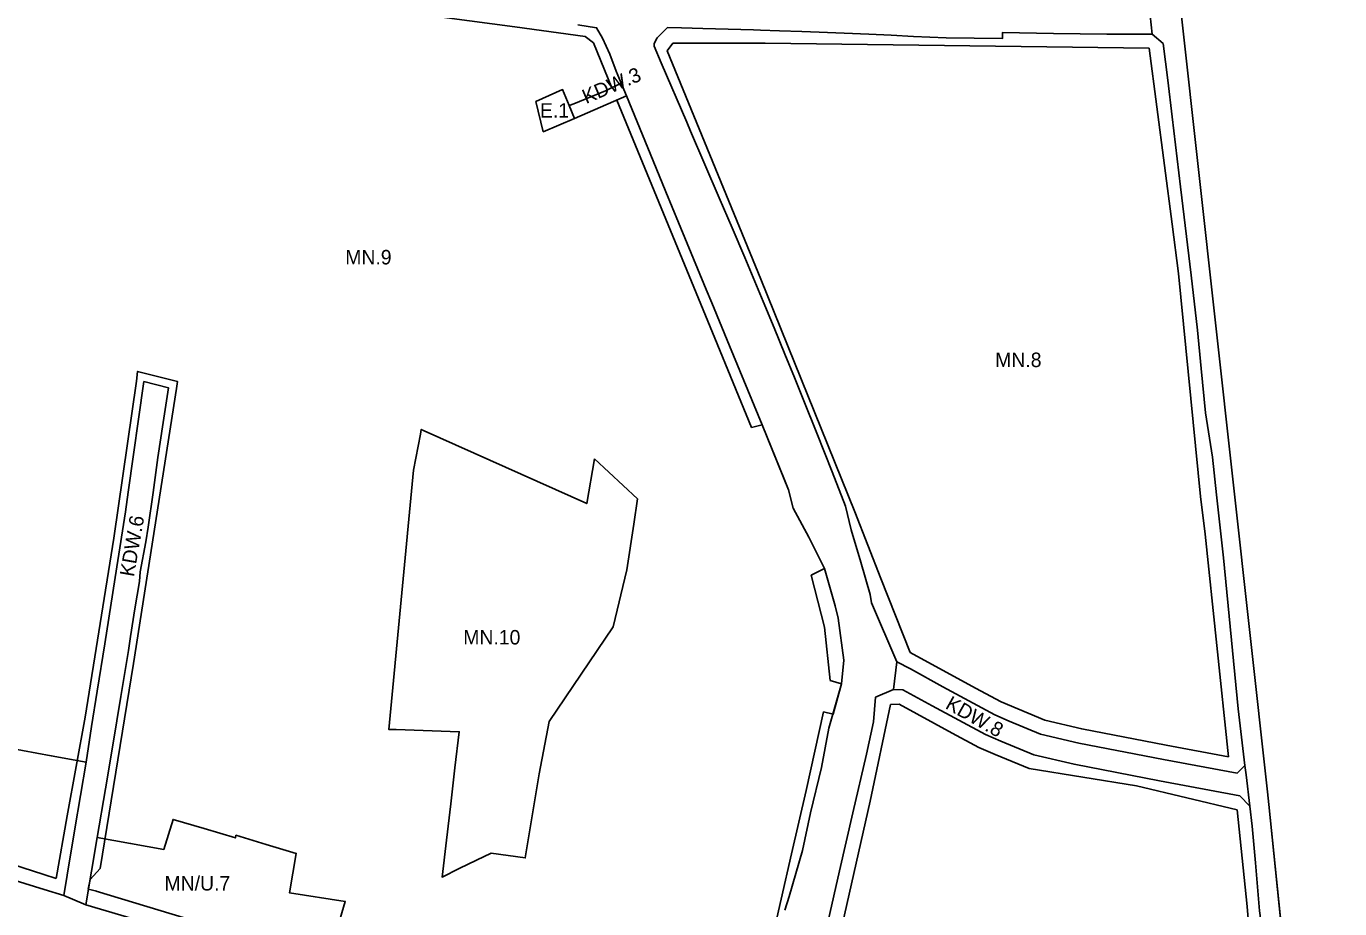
# Model space of a CAD drawing. Extents: x 7423274 to 7424514, y 5542390 to 5544261.
# Drawn here: x 7423885.8 to 7424248, y 5543366 to 5543609.4 of the extents above; entities that cross this region are included whole.
import ezdxf

# ---------------------------------------------------------------- set-up
doc = ezdxf.new("R2010")
doc.units = 0
for name, color, linetype in [('granica obszaru objętego planem', 7, 'Continuous'), ('LIN_Granica Planu', 7, 'Continuous'), ('linie rozgraniczające tereny o różnym przeznaczeniu lub różnych zasadach zagospodarowania', 7, 'Continuous'), ('nieprzekraczalna linia zabudowy', 7, 'Continuous'), ('oznaczenia terenów', 7, 'Continuous')]:
    doc.layers.add(name, color=color, linetype=linetype)

msp = doc.modelspace()

# ---------------------------------------------------------------- linework, layer by layer
at = {"layer": 'granica obszaru objętego planem'}
for p, q in [((7424204.36, 5543612.15), (7424228.15, 5543398.17)), ((7424228.15, 5543398.17), (7424228.51, 5543394.73)), ((7424228.51, 5543394.73), (7424242.62, 5543256.86))]:
    msp.add_line(p, q, dxfattribs=at)
at = {"layer": 'LIN_Granica Planu'}
for p, q in [((7424228.15, 5543398.17), (7424204.36, 5543612.15)), ((7424228.51, 5543394.73), (7424228.15, 5543398.17)), ((7424242.62, 5543256.86), (7424228.51, 5543394.73))]:
    msp.add_line(p, q, dxfattribs=at)
at = {"layer": 'linie rozgraniczające tereny o różnym przeznaczeniu lub różnych zasadach zagospodarowania'}
for p, q in [((7424195.16, 5543618.28), (7424196.31, 5543607.23)), ((7424036.98, 5543583.98), (7424051.34, 5543590.15))]:
    msp.add_line(p, q, dxfattribs=at)
for points in [[(7424129.39, 5544001.9), (7424129.8, 5543999.91), (7424131.7, 5543990.87), (7424133.97, 5543980.01), (7424148.11, 5543912.49), (7424163.08, 5543838.56), (7424169.46, 5543807.01), (7424175.57, 5543776.81), (7424186.15, 5543728.82), (7424192.74, 5543698.89), (7424202.07, 5543636.25), (7424204.36, 5543612.15), (7424228.15, 5543398.17), (7424228.51, 5543394.73), (7424242.62, 5543256.86), (7424248.04, 5543257.08)], [(7424037.96, 5543609.76), (7424043.11, 5543608.99), (7424044.74, 5543606.11), (7424046.74, 5543601.68), (7424048.53, 5543597), (7424049.9, 5543593.66)], [(7424125.94, 5543434.02), (7424118.89, 5543450.32), (7424118.56, 5543452.65), (7424115.95, 5543461.55), (7424113.34, 5543470.45), (7424111.76, 5543477.01), (7424108.05, 5543486.45), (7424103.86, 5543497.1), (7424100.24, 5543506.07), (7424097.65, 5543512.5), (7424095.05, 5543518.92), (7424092.04, 5543526.17), (7424089.03, 5543533.43), (7424083.99, 5543545.58), (7424080.46, 5543553.81), (7424076.92, 5543562.04), (7424069, 5543580.48), (7424067.95, 5543582.94), (7424060.94, 5543599.26), (7424059.02, 5543603.89), (7424058.97, 5543604.62), (7424059.79, 5543606.15), (7424062.64, 5543609), (7424066.54, 5543608.91), (7424069.47, 5543608.83), (7424072.4, 5543608.75), (7424079.41, 5543608.56), (7424086.42, 5543608.37), (7424088.27, 5543608.33), (7424093.54, 5543608.16), (7424099.74, 5543607.95), (7424102.12, 5543607.87), (7424104.51, 5543607.79), (7424111.35, 5543607.48), (7424118.19, 5543607.16), (7424124.36, 5543606.88), (7424130.53, 5543606.59), (7424135.03, 5543606.38), (7424139.53, 5543606.18), (7424147.27, 5543606.08), (7424155, 5543605.97), (7424155, 5543607.63), (7424169.1, 5543607.38), (7424176.45, 5543607.3), (7424183.79, 5543607.23), (7424196.31, 5543607.23)], [(7424062.64, 5543609), (7424062.64, 5543609)], [(7424183.79, 5543607.23), (7424183.79, 5543607.23)], [(7424196.31, 5543607.23), (7424199.37, 5543604.59), (7424200.59, 5543594.48), (7424201.82, 5543584.37), (7424204.16, 5543565.07), (7424207.11, 5543540.74), (7424208.8, 5543525.54), (7424209.82, 5543514.99), (7424210.99, 5543502.76), (7424212.93, 5543490.48), (7424214.06, 5543480.17), (7424216.01, 5543462.75), (7424220.04, 5543421.12), (7424221.9, 5543405.42)], [(7424049.9, 5543593.66), (7424045.57, 5543591.56), (7424036.87, 5543588.02), (7424035.55, 5543587.48)], [(7424049.9, 5543593.66), (7424051.34, 5543590.15)], [(7424035.55, 5543587.48), (7424033.73, 5543591.92), (7424030.04, 5543590.25), (7424026.36, 5543588.59), (7424028.4, 5543580.29), (7424032.69, 5543582.13), (7424036.98, 5543583.98)], [(7424051.34, 5543590.15), (7424058.7, 5543572.26), (7424062.2, 5543563.75), (7424065.7, 5543555.23), (7424073.3, 5543536.76), (7424074.84, 5543533.06), (7424079.75, 5543521.24), (7424088.72, 5543499.41), (7424094.76, 5543484.71), (7424096.03, 5543481.46), (7424097.35, 5543476.46), (7424101.62, 5543468.49), (7424106, 5543459.76), (7424108.91, 5543449.49), (7424109.7, 5543446.06), (7424111.33, 5543434.5), (7424110.64, 5543428.03), (7424107.14, 5543415.72), (7424105.13, 5543404.88), (7424102.13, 5543392.36), (7424099.9, 5543381.97), (7424096.17, 5543369.34), (7424095.06, 5543365.57)], [(7424035.55, 5543587.48), (7424036.98, 5543583.98)], [(7423905.4, 5543385.58), (7423907.67, 5543399.07), (7423909.69, 5543411.08), (7423911.89, 5543424.5), (7423913.98, 5543437.2), (7423914.54, 5543441.02), (7423915.79, 5543448.64), (7423917.05, 5543456.26), (7423917.27, 5543458.85), (7423918.77, 5543467.19), (7423919.48, 5543471.18), (7423920.8, 5543480.79), (7423922.13, 5543490.39), (7423923.57, 5543500.04), (7423925.01, 5543509.68), (7423918.27, 5543511.38), (7423918.27, 5543511.37), (7423913.94, 5543480.85), (7423913.17, 5543475.41), (7423910.78, 5543460.22), (7423907.46, 5543439.05), (7423905.4, 5543425.99), (7423903.86, 5543416.19), (7423902.32, 5543406.39)], [(7424042.54, 5543490.03), (7424040.38, 5543477.73), (7423995.58, 5543497.82), (7423994.75, 5543498.16), (7423994.5, 5543496.87), (7423992.59, 5543486.91), (7423989.19, 5543451.16), (7423985.79, 5543415.41), (7423987.79, 5543415.35), (7424005.23, 5543414.79), (7424004.05, 5543404.86), (7424002.88, 5543394.93), (7424001.68, 5543384.82), (7424000.48, 5543374.7), (7424005.25, 5543377.01), (7424010.02, 5543379.32), (7424014.05, 5543381.28), (7424018.75, 5543380.63), (7424023.44, 5543379.98), (7424024.84, 5543388.81), (7424027.28, 5543403.16), (7424029.98, 5543417.58), (7424047.66, 5543443.74), (7424051.4, 5543459.48), (7424053.33, 5543472.01), (7424054.41, 5543479.02), (7424042.54, 5543490.03)], [(7423762.1, 5543471.78), (7423763.2, 5543470.95), (7423772.9, 5543465.5), (7423780.62, 5543462.22), (7423788.34, 5543458.94), (7423794.18, 5543472.69), (7423802.28, 5543468.74), (7423810.38, 5543464.78), (7423806.73, 5543456.67), (7423803.07, 5543448.57), (7423810.25, 5543445.33), (7423819.48, 5543441.05), (7423824.09, 5543438.92), (7423829.37, 5543437.42), (7423834.65, 5543435.93), (7423831.92, 5543426.28), (7423830.43, 5543420.98), (7423849.77, 5543416.04), (7423868.85, 5543412.52), (7423892.72, 5543408.15), (7423902.32, 5543406.39)], [(7424124.99, 5543426.4), (7424125.94, 5543434.02)], [(7424125.94, 5543434.02), (7424129.66, 5543432.17), (7424138.57, 5543427.18), (7424152.95, 5543419.4), (7424156.89, 5543417.67), (7424165.5, 5543414.14), (7424176.06, 5543411.66), (7424199.45, 5543407.1), (7424219.74, 5543403.36), (7424221.9, 5543405.42)], [(7424092.5, 5543275.06), (7424095.41, 5543303.55), (7424095.87, 5543307.37), (7424097.46, 5543318.57), (7424098.68, 5543326.94), (7424100.22, 5543333.4), (7424101.76, 5543339.86), (7424103.33, 5543346.79), (7424104.9, 5543353.71), (7424110.13, 5543376.43), (7424113.79, 5543392.37), (7424117.5, 5543408.62), (7424119.5, 5543417.47), (7424120.06, 5543424.28), (7424124.99, 5543426.4)], [(7424120.06, 5543424.28), (7424120.06, 5543424.28)], [(7424124.99, 5543426.4), (7424127.58, 5543426.33), (7424135.67, 5543421.93), (7424150.31, 5543414), (7424154.55, 5543412.15), (7424163.66, 5543408.41), (7424174.8, 5543405.79), (7424198.34, 5543401.2), (7424220.49, 5543397.12), (7424223.21, 5543394.21)], [(7423902.32, 5543406.39), (7423899.26, 5543387.98), (7423897.13, 5543375.17), (7423896.2, 5543369.56)], [(7424223.21, 5543394.21), (7424222.2, 5543402.91), (7424221.9, 5543405.42)], [(7424230.35, 5543322.31), (7424228.43, 5543342.33), (7424226.86, 5543358.67), (7424225.94, 5543365.33), (7424224.84, 5543378.57), (7424223.86, 5543388.69), (7424223.21, 5543394.21)], [(7423968.62, 5543350.36), (7423973.77, 5543367.98), (7423958.39, 5543370.37), (7423960.3, 5543381.21), (7423951.96, 5543383.71), (7423943.62, 5543386.21), (7423943.52, 5543385.47), (7423934.92, 5543388.04), (7423926.32, 5543390.6), (7423925.03, 5543386.46), (7423923.73, 5543382.33), (7423914.57, 5543383.96), (7423905.4, 5543385.58)], [(7423902.29, 5543367.06), (7423905.4, 5543385.58)], [(7423896.2, 5543369.56), (7423890.76, 5543371.25), (7423880.07, 5543374.56)], [(7423902.29, 5543367.06), (7423898.57, 5543368.58), (7423896.2, 5543369.56)], [(7423952.21, 5543354.3), (7423949.45, 5543354.66), (7423934.63, 5543357.19), (7423917.53, 5543362.55), (7423902.29, 5543367.06)]]:
    msp.add_lwpolyline(points, dxfattribs=at)
at = {"layer": 'nieprzekraczalna linia zabudowy'}
for p, q in [((7423927.26, 5543509.46), (7423915.44, 5543433.6)), ((7424088.72, 5543499.41), (7424085.83, 5543498.69)), ((7424102.29, 5543457.94), (7424106, 5543459.76)), ((7424107.56, 5543428.93), (7424105.97, 5543443.6)), ((7423890.69, 5543375.39), (7423894.07, 5543374.28))]:
    msp.add_line(p, q, dxfattribs=at)
for points in [[(7424039.93, 5543606.59), (7424020.52, 5543609.24), (7423987.89, 5543613.53), (7423960.85, 5543617.16), (7423923.09, 5543622.46), (7423913.13, 5543624.02), (7423890.12, 5543627.03)], [(7424047.33, 5543592.41), (7424042.23, 5543604.85), (7424039.93, 5543606.59)], [(7424064.11, 5543604.74), (7424062.61, 5543602.56), (7424088.41, 5543539.58), (7424114.34, 5543475.48), (7424121.46, 5543457.07), (7424121.46, 5543457.07), (7424121.46, 5543457.07)], [(7424195.49, 5543603.36), (7424089.63, 5543604.68), (7424064.11, 5543604.74)], [(7424217.33, 5543407.87), (7424210.94, 5543469.23), (7424209.66, 5543479.71), (7424203.54, 5543541.2), (7424201.83, 5543554.81), (7424195.49, 5543603.36)], [(7424085.83, 5543498.69), (7424075.7, 5543523.31), (7424048.73, 5543589.02)], [(7423916.2, 5543511.49), (7423916.52, 5543514.19), (7423927.56, 5543511.35), (7423927.26, 5543509.46)], [(7423894.07, 5543374.28), (7423897.1, 5543391.62), (7423902.07, 5543418.84), (7423910, 5543468.18), (7423916.2, 5543511.49)], [(7424106, 5543459.76), (7424101.62, 5543468.49), (7424097.35, 5543476.46), (7424096.03, 5543481.46), (7424088.72, 5543499.41)], [(7424105.97, 5543443.6), (7424105.97, 5543443.6), (7424102.29, 5543457.94), (7424102.29, 5543457.94)], [(7424121.46, 5543457.07), (7424129.62, 5543436.66), (7424147.6, 5543426.84), (7424154.7, 5543422.99), (7424166.72, 5543417.96), (7424176.9, 5543415.57), (7424200.2, 5543411.03), (7424217.33, 5543407.87)], [(7423737.24, 5543436.72), (7423752.7, 5543428.57), (7423752.7, 5543428.57), (7423809.8, 5543401.5), (7423890.69, 5543375.39)], [(7423915.44, 5543433.6), (7423915.44, 5543433.6), (7423915.44, 5543433.6), (7423915.44, 5543433.6), (7423906.16, 5543377.02), (7423906.16, 5543377.02), (7423906.16, 5543377.02)], [(7424105.72, 5543420.31), (7424108.3, 5543419.64), (7424110.64, 5543428.03), (7424107.53, 5543428.95)], [(7424096.87, 5543381.11), (7424100.87, 5543398.54), (7424105.72, 5543420.31)], [(7424124.14, 5543422.33), (7424118.57, 5543395.65), (7424102.67, 5543325.15), (7424100.54, 5543325.49)], [(7424219.76, 5543393.19), (7424192.01, 5543399.84), (7424162.44, 5543404.59), (7424152.99, 5543408.46), (7424148.56, 5543410.4), (7424141.16, 5543414.41), (7424126.51, 5543422.35), (7424124.14, 5543422.33)], [(7424224.15, 5543346.3), (7424224.15, 5543346.3), (7424222.51, 5543366.56), (7424219.76, 5543393.19)], [(7424082.19, 5543317.08), (7424084.25, 5543326.09), (7424088.18, 5543342.9), (7424091.18, 5543356.07), (7424096.87, 5543381.11)], [(7423906.16, 5543377.02), (7423903.49, 5543374.01), (7423902.92, 5543371.39), (7423905.26, 5543370.77)], [(7423905.14, 5543370.81), (7423940.04, 5543360.21), (7423954.31, 5543356.07), (7423976.39, 5543350.12)]]:
    msp.add_lwpolyline(points, dxfattribs=at)

# ---------------------------------------------------------------- texts
at = {"layer": 'oznaczenia terenów'}
for s, rotation, p in [('KDW.3', 23.0794, (7424040.2, 5543587.91)), ('KDW.6', 80.1215, (7423915.49, 5543457.35)), ('KDW.8', 330.7816, (7424139.02, 5543421.35))]:
    msp.add_text(s, height=4, rotation=rotation, dxfattribs=at).set_placement(p)
for s, p in [('E.1', (7424027.49, 5543584.16)), ('MN.9', (7423973.79, 5543543.68)), ('MN.8', (7424153.02, 5543515.36)), ('MN.10', (7424006.33, 5543438.84)), ('MN/U.7', (7423923.95, 5543370.98))]:
    msp.add_text(s, height=4, dxfattribs=at).set_placement(p)

doc.saveas('drawing.dxf')
